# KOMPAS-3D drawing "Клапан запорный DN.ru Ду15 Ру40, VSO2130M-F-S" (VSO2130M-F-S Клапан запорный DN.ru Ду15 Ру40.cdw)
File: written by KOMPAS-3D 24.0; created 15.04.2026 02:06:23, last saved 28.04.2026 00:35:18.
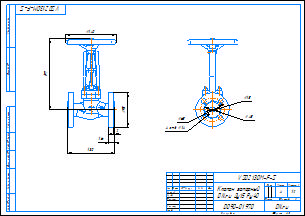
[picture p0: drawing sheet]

Document properties: Автор: DN.ru; Форматы листов документа: A3; Полное имя файла: VSO2130M-F-S Клапан запорный DN.ru Ду15 Ру40.m3d; Масса: 4; Наименование: Клапан запорный DN.ru Ду15 Ру40; Количество листов документа: 1; Примечание: D090-01970

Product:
- Part/product: Клапан запорный DN.ru Ду15 Ру40  | designation VSO2130M-F-S
    Масса: 4
    Раздел спецификации: Прочие изделия
    Примечание: D090-01970

Views: Проекционный вид 2, Вид:1
Referenced files in C:\Работа\VSO2130M-F-S Клапан запорный DN.ru\DN15\: VSO2130M-F-S DN15 PN40  Клапан запорный сильфонный DN.ru.m3d, VSO2130M-F-S Клапан запорный DN.ru Ду15 Ру40.m3d
Referenced files in C:\Program Files\ASCON\KOMPAS-3D v24\Templates\: Чертеж_DN.ru.cdt
Referenced files in C:\Работа\ГОТОВЫЕ ИСХОДНИКИ\VSO2130M-F-S Клапан запорный сильфонный DN.ru Ду15-100 Ру40\DN15\: VSO2130M-F-S Клапан запорный DN.ru Ду15 Ру40.m3d
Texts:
  VSO2130M-F-S
  Чертеж_DN.ru.cdt
  Клапан запорный
  DN.ru Ду15 Ру40
  Клапан запорный DN.ru Ду15 Ру40
  VSO2130M-F-S  Клапан запорный DN.ru Ду15 Ру40
Dimensions and other numbers on the sheet: 0; 3; 5; 4; 15; 45; 65; 4 отв.; 14; 1:2; 1; 2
